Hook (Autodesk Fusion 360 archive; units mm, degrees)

design "Hook" references "Base"
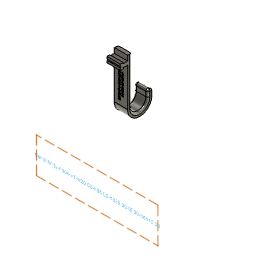
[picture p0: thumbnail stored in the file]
parameter "width" = 20
parameter "height" = 88
parameter "hook_diameter" = 36
parameter "thickness" = 6
parameter "hook_end_height" = 10
component_insert "Component Insert"
sketch "Sketch1" plane through (0, 55.6118, 0) normal (0, 1, 0) x axis (-1, 0, 0)
  line L1 (0, 52.6059) -> (-48, 52.6059)
  line L2 (0, 60) -> (0, 52.6059)
  line L3 (-48, 60) -> (0, 60)
  line L4 (-48, 52.6059) -> (-48, 60)
  line L5 (-48, 60) -> (0, 60)
sketch "Sketch2" plane through (0, 0, 0) normal (1, 0, 0) x axis (0, 1, 0)
  line L1 (55.6118, -28) -> (55.6118, 60)
  line L2 (91.6118, -28) -> (55.6118, -28)
  line L3 (91.6118, 8) -> (91.6118, -28)
  line L4 (55.6118, -28) -> (91.6118, 8)
  line L5 (91.6118, -10) -> (55.6118, -10)
  line L6 (61.6118, -28) -> (61.6118, 60)
  line L7 (61.6118, 59.3739) -> (55.6118, 60)
  circle C1 centre (73.6118, -10) radius 18
  circle C2 centre (73.6118, -10) radius 12
  point P2 (55.6118, 60)
  point P3 (55.6118, 60)
  point P7 (73.6118, -10)
  point P8 (55.6118, -10)
  point P9 (91.6118, -10)
  point P13 (55.6118, 60)
  point P14 (61.6118, 59.3739)
  point P4 (55.6118, -28)
  point P5 (91.6118, -28)
  point P6 (91.6118, 8)
  coincident P2 P3
  vertical L1
  perpendicular L1 L2
  perpendicular L2 L3
  midpoint L4 P7
  coincident L1 P8
  coincident C1 P8
  midpoint L3 P9
  perpendicular L3 L5
  coincident P2 P13
  coincident L6 P14
  dimension "d5" distance P3 P4 = 88 (= "height")
  dimension "d6" distance P4 P5 = 36 (= "hook_diameter")
  dimension "d8" distance P5 P6 = 36 (= "hook_diameter")
  dimension "d9" diameter C1 = 36 (= "hook_diameter")
  dimension "d11" = -6 (= "thickness * -1")
  dimension "d12" = -6 (= "thickness * -1")
extrude "Extrude1" new body sketch "Sketch2" profile of L1 C1 L5 L6 C2 L7 along normal blind 20 (= "width")
extrude "Extrude2" add of existing geometry blind 10 (= "hook_end_height")
fillet "Fillet1" radius 3 (= "thickness / 2")
extrude "Extrude3" new body of existing geometry blind 29
extrude "Extrude4" add of existing geometry to an object
extrude "Extrude5" cut of existing geometry to an object
sketch "Text" plane through (0, 55.6118, 0) normal (0, -1, 0) x axis (1, 0, 0)
  dimension "d29" = 3 (= "( if(height < 70 mm; if(height < 41 mm; 1.2; 2); 3) ) * 1 mm")
  dimension "d30" = 20 (= "width")
extrude "Extrude6" cut sketch "Text" against normal blind 2
sketch "Filename" plane through (0, 0, 0) normal (0, 1, 0) x axis (1, 0, 0)
  dimension "d31" = 5

design "Base"
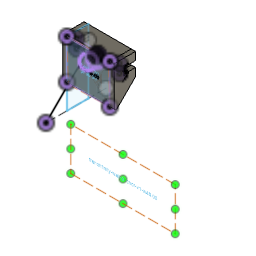
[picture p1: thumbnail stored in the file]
parameter "wall_anchor_height" = 60
parameter "wall_anchor_width" = 20
parameter "wall_anchor_angle" = 45
parameter "width_per_slot" = 40
parameter "slot_inner_width" = 8.5
parameter "slot_inner_height" = 4.5
parameter "slot_outer_width" = 5.6
parameter "slot_outer_height" = 6.5
parameter "slot_dept" = 15
parameter "print_tolerance" = 0.12
parameter "base_plate_thickness" = 16
parameter "base_plate_slot_height" = 50
parameter "wall_anchor_angle_rounded_border" = 1.5
parameter "base_plate_screw_hole_diameter" = 4
parameter "base_plate_screw_head_diameter" = 8
parameter "base_plate_screw_head_height" = 4
parameter "base_plate_screw_hole_side_distance" = 7
parameter "slot_screw_head_width" = 4.42 (= "4.3 mm + print_tolerance")
parameter "slot_screw_thread_width" = 2.12 (= "2 mm + print_tolerance")
parameter "slot_screw_head_height" = 2.12 (= "2 mm + print_tolerance")
parameter "width" = 48
parameter "filament_hole_width" = 1.7
parameter "plate_height" = 50
sketch "Side" plane through (0, 0, 0) normal (1, 0, 0) x axis (0, 1, 0)
  line L1 (39.6118, 0) -> (19.6118, 0)
  line L2 (39.6118, 60) -> (39.6118, 0)
  line L3 (19.6118, 60) -> (39.6118, 60)
  line L4 (19.6118, 0) -> (19.6118, 60)
  line L5 (39.6118, 39.6118) -> (0, 0)
  line L6 (56.0196, 0) -> (0, 0)
  point P1 (0, 0)
  point P6 (0, 0)
  point P7 (39.6118, 39.6118)
  point P2 (19.6118, 0)
  point P3 (39.6118, 0)
  point P5 (19.6118, 60)
  horizontal L1
  vertical L2
  horizontal L3
  vertical L4
  horizontal L6
  coincident P1 P6
  coincident L2 P7
  dimension "d4" distance P2 P3 = 20 (= "wall_anchor_width")
  dimension "d5" distance P2 P5 = 60 (= "wall_anchor_height")
  dimension "d6" angle L5 L6 = 45 (= "wall_anchor_angle")
extrude "Extrude1" new body sketch "Side" profile of L1 L2 L3 L4 L5 along normal blind 40 (= "width_per_slot")
sketch "Slot LeftToRight" plane through (0, 0, 0) normal (-1, 0, 0) x axis (0, -1, 0)
  line L1 (-19.6118, 60) -> (-19.6118, 19.6118)
  line L2 (-39.6118, 60) -> (-19.6118, 60)
  line L3 (-39.6118, 39.6118) -> (-39.6118, 60)
  line L4 (-19.6118, 19.6118) -> (-39.6118, 39.6118)
  line L5 (-39.6118, 52.6059) -> (-39.6118, 49.8059)
  line L6 (-39.6118, 47.0059) -> (-39.6118, 49.8059)
  line L7 (-33.1118, 52.6059) -> (-39.6118, 52.6059)
  line L8 (-28.6118, 49.8059) -> (-39.6118, 49.8059)
  line L9 (-28.6118, 54.0559) -> (-28.6118, 49.8059)
  line L10 (-33.1118, 54.0559) -> (-28.6118, 54.0559)
  line L11 (-33.1118, 52.6059) -> (-33.1118, 54.0559)
  line L12 (-28.6118, 45.5559) -> (-28.6118, 49.8059)
  line L13 (-33.1118, 45.5559) -> (-28.6118, 45.5559)
  line L14 (-33.1118, 47.0059) -> (-33.1118, 45.5559)
  line L15 (-33.1118, 47.0059) -> (-39.6118, 47.0059)
  point P6 (-39.6118, 49.8059)
  point P7 (-39.6118, 52.6059)
  point P17 (-39.6118, 47.0059)
  point P9 (-33.1118, 52.6059)
  point P16 (-33.1118, 47.0059)
  point P10 (-28.6118, 49.8059)
  point P13 (-28.6118, 49.8059)
  point P11 (-28.6118, 54.0559)
  point P14 (-28.6118, 45.5559)
  point P12 (-33.1118, 54.0559)
  point P15 (-33.1118, 45.5559)
  midpoint L3 P6
  parallel L3 L5
  parallel L3 L6
  perpendicular L3 L7
  perpendicular L6 L8
  perpendicular L8 L9
  perpendicular L9 L10
  symmetric P7 L8 P17
  symmetric P9 L8 P16
  symmetric P10 L8 P13
  symmetric L8 P11 P14
  symmetric L8 P12 P15
  dimension "d80" distance P6 P7 = 2.8 (= "slot_outer_width / 2")
  dimension "d82" distance P7 P9 = 6.5 (= "slot_outer_height")
  dimension "d84" distance P6 P10 = 11 (= "slot_outer_height + slot_inner_height")
  dimension "d85" distance P10 P11 = 4.25 (= "slot_inner_width / 2")
  dimension "d86" distance P11 P12 = 4.5 (= "slot_inner_height")
extrude "Extrude3" cut sketch "Slot LeftToRight" profile of L3 L5 L6 L7 L9 L10 L11 L12 L13 L14 L15 against normal blind 40 (magnitude of "width_per_slot * -1")
sketch "Plate" plane through (0, 39.6118, 0) normal (0, 1, 0) x axis (-1, 0, 0)
  line L1 (0, 39.6118) -> (-40, 39.6118)
  line L2 (-40, 60) -> (0, 60)
  line L3 (0, 10) -> (0, 60)
  line L4 (-40, 10) -> (-40, 60)
  line L5 (-40, 10) -> (0, 10)
  line L6 (-40, 47.0059) -> (0, 47.0059)
  line L7 (-40, 52.6059) -> (-40, 60)
  line L8 (0, 60) -> (0, 52.6059)
  line L9 (0, 52.6059) -> (-40, 52.6059)
  line L10 (-40, 60) -> (0, 60)
  line L11 (-40, 39.6118) -> (-40, 47.0059)
  line L12 (0, 47.0059) -> (0, 39.6118)
  point P2 (0, 60)
  point P3 (-40, 60)
  point P4 (0, 10)
  point P5 (-40, 10)
  perpendicular L1 L3
  perpendicular L1 L4
  dimension "d36" distance P2 P3 = 40 (= "width_per_slot")
  dimension "d37" distance P2 P4 = 50 (= "base_plate_slot_height")
  dimension "d39" distance P3 P5 = 50 (= "base_plate_slot_height")
extrude "Extrude6" new body sketch "Plate" profile of L1 L2 L3 L4 L5 L6 L7 L8 L9 L10 along normal blind 16 (= "base_plate_thickness") bodies "Base plate with slot"
sketch "Slot" plane through (0, 0, 0) normal (-1, 0, 0) x axis (0, -1, 0)
  line L1 (-19.6118, 60) -> (-19.6118, 19.6118)
  line L2 (-39.6118, 60) -> (-19.6118, 60)
  line L3 (-39.6118, 52.6059) -> (-39.6118, 60)
  line L4 (-33.1118, 52.6059) -> (-39.6118, 52.6059)
  line L5 (-33.1118, 54.0559) -> (-33.1118, 52.6059)
  line L6 (-28.6118, 54.0559) -> (-33.1118, 54.0559)
  line L7 (-28.6118, 45.5559) -> (-28.6118, 54.0559)
  line L8 (-33.1118, 45.5559) -> (-28.6118, 45.5559)
  line L9 (-33.1118, 47.0059) -> (-33.1118, 45.5559)
  line L10 (-39.6118, 47.0059) -> (-33.1118, 47.0059)
  line L11 (-39.6118, 39.6118) -> (-39.6118, 47.0059)
  line L12 (-19.6118, 19.6118) -> (-39.6118, 39.6118)
  line L13 (-33.1118, 52.6059) -> (-39.6118, 52.6059)
  line L14 (-33.1118, 54.0559) -> (-33.1118, 52.6059)
  line L15 (-28.6118, 54.0559) -> (-33.1118, 54.0559)
  line L16 (-28.6118, 45.5559) -> (-28.6118, 54.0559)
  line L17 (-33.1118, 45.5559) -> (-28.6118, 45.5559)
  line L18 (-33.1118, 47.0059) -> (-33.1118, 45.5559)
  line L19 (-39.6118, 47.0059) -> (-33.1118, 47.0059)
  line L20 (-39.6118, 10) -> (-39.6118, 60)
  line L21 (-32.9918, 52.4859) -> (-39.6118, 52.4859)
  line L22 (-32.9918, 53.9359) -> (-32.9918, 52.4859)
  line L23 (-28.7318, 53.9359) -> (-32.9918, 53.9359)
  line L24 (-28.7318, 45.6759) -> (-28.7318, 53.9359)
  line L25 (-32.9918, 45.6759) -> (-28.7318, 45.6759)
  line L26 (-32.9918, 47.1259) -> (-32.9918, 45.6759)
  line L27 (-39.6118, 47.1259) -> (-32.9918, 47.1259)
  line L28 (-33.1118, 52.6059) -> (-39.6118, 52.6059)
  line L29 (-33.1118, 52.6059) -> (-33.1118, 54.0559)
  line L30 (-28.6118, 54.0559) -> (-33.1118, 54.0559)
  line L31 (-28.6118, 45.5559) -> (-28.6118, 54.0559)
  line L32 (-33.1118, 45.5559) -> (-28.6118, 45.5559)
  line L33 (-33.1118, 47.0059) -> (-33.1118, 45.5559)
  line L34 (-39.6118, 47.0059) -> (-33.1118, 47.0059)
  line L35 (-39.6118, 47.0059) -> (-39.6118, 52.6059)
  line L36 (-49.1118, 52.6059) -> (-55.6118, 52.6059)
  line L37 (-49.1118, 52.6059) -> (-49.1118, 54.0559)
  line L38 (-44.6118, 54.0559) -> (-49.1118, 54.0559)
  line L39 (-44.6118, 45.5559) -> (-44.6118, 54.0559)
  line L40 (-49.1118, 45.5559) -> (-44.6118, 45.5559)
  line L41 (-49.1118, 47.0059) -> (-49.1118, 45.5559)
  line L42 (-55.6118, 47.0059) -> (-49.1118, 47.0059)
  line L43 (-55.6118, 47.0059) -> (-55.6118, 52.6059)
  point P15 (-39.6118, 52.6059)
  point P33 (-39.6118, 52.6059)
  point P16 (-33.1118, 52.6059)
  point P34 (-33.1118, 52.6059)
  point P17 (-33.1118, 54.0559)
  point P35 (-33.1118, 54.0559)
  point P36 (-33.1118, 52.6059)
  point P18 (-28.6118, 54.0559)
  point P37 (-28.6118, 54.0559)
  point P19 (-28.6118, 45.5559)
  point P38 (-28.6118, 45.5559)
  point P10 (-28.6118, 45.5559)
  point P39 (-28.6118, 45.5559)
  point P11 (-33.1118, 45.5559)
  point P40 (-33.1118, 45.5559)
  point P41 (-33.1118, 45.5559)
  point P12 (-33.1118, 47.0059)
  point P42 (-33.1118, 47.0059)
  point P21 (-33.1118, 47.0059)
  point P43 (-33.1118, 47.0059)
  point P22 (-39.6118, 47.0059)
  point P44 (-39.6118, 47.0059)
  point P45 (-39.6118, 52.6059)
  point P46 (-39.6118, 47.0059)
  coincident P15 P33
  coincident P16 P34
  coincident P17 P35
  coincident P16 P36
  coincident P18 P37
  coincident P19 P38
  coincident P10 P39
  coincident P11 P40
  coincident P11 P41
  coincident P12 P42
  coincident P21 P43
  coincident P22 P44
  coincident P15 P45
  coincident P22 P46
  dimension "d91" = 0.12 (= "print_tolerance")
  dimension "d96" R-Pattern1-uDistance = -16 (= "base_plate_thickness * -1")
  dimension "d97" R-Pattern1-vDistance = 0
extrude "Extrude7" add sketch "Slot" profile of L20 L24 L23 L27 L22 L25 L26 L21 against normal blind 40 (magnitude of "width_per_slot * -1")
extrude "Extrude8" cut sketch "Slot" profile of L36 L37 L38 L39 L40 L41 L42 L43 no distance stored
sketch "Sketch3" plane through (0, 0, 0) normal (-1, 0, 0) x axis (0, -1, 0)
  line L1 (-32.9918, 47.1259) -> (-39.6118, 47.1259)
  line L2 (-32.9918, 45.6759) -> (-32.9918, 47.1259)
  line L3 (-28.7318, 45.6759) -> (-32.9918, 45.6759)
  line L4 (-28.7318, 53.9359) -> (-28.7318, 45.6759)
  line L5 (-32.9918, 53.9359) -> (-28.7318, 53.9359)
  line L6 (-32.9918, 52.4859) -> (-32.9918, 53.9359)
  line L7 (-39.6118, 52.4859) -> (-32.9918, 52.4859)
  line L8 (-44.6118, 45.5559) -> (-44.6118, 54.0559)
  line L9 (-32.9918, 52.4859) -> (-39.6118, 52.4859)
  line L10 (-32.9918, 53.9359) -> (-32.9918, 52.4859)
  line L11 (-28.7318, 53.9359) -> (-32.9918, 53.9359)
  line L12 (-28.7318, 45.6759) -> (-28.7318, 53.9359)
  line L13 (-32.9918, 45.6759) -> (-28.7318, 45.6759)
  line L14 (-32.9918, 47.1259) -> (-32.9918, 45.6759)
  line L15 (-39.6118, 47.1259) -> (-32.9918, 47.1259)
  line L16 (-39.6118, 47.1259) -> (-39.6118, 52.4859)
  line L17 (-55.6118, 52.4859) -> (-48.9918, 52.4859)
  line L18 (-48.9918, 52.4859) -> (-48.9918, 53.9359)
  line L19 (-48.9918, 53.9359) -> (-44.7318, 53.9359)
  line L20 (-44.7318, 45.6759) -> (-44.7318, 53.9359)
  line L21 (-48.9918, 45.6759) -> (-44.7318, 45.6759)
  line L22 (-48.9918, 47.1259) -> (-48.9918, 45.6759)
  line L23 (-55.6118, 47.1259) -> (-48.9918, 47.1259)
  line L24 (-55.6118, 47.1259) -> (-55.6118, 52.4859)
  line L25 (-55.6118, 47.0059) -> (-49.1118, 47.0059)
  line L26 (-55.6118, 10) -> (-55.6118, 47.0059)
  line L27 (-39.6118, 10) -> (-55.6118, 10)
  line L28 (-39.6118, 47.1259) -> (-39.6118, 10)
  line L29 (-39.6118, 60) -> (-39.6118, 52.4859)
  line L30 (-55.6118, 60) -> (-39.6118, 60)
  line L31 (-55.6118, 52.6059) -> (-55.6118, 60)
  line L32 (-49.1118, 52.6059) -> (-55.6118, 52.6059)
  line L33 (-49.1118, 54.0559) -> (-49.1118, 52.6059)
  line L34 (-44.6118, 54.0559) -> (-49.1118, 54.0559)
  line L35 (-49.1118, 45.5559) -> (-44.6118, 45.5559)
  line L36 (-49.1118, 47.0059) -> (-49.1118, 45.5559)
  point P9 (-39.6118, 52.4859)
  point P20 (-39.6118, 52.4859)
  point P19 (-39.6118, 47.1259)
  point P21 (-39.6118, 47.1259)
  coincident P9 P20
  coincident P19 P21
  dimension "d105" R-Pattern1-vDistance = 0
extrude "Extrude3" new body sketch "Sketch3" profile of L17 L18 L19 L20 L21 L22 L23 L24 against normal blind 40 (magnitude of "width_per_slot * -1")
sketch "Screw hole" plane through (0, 28.6118, 0) normal (0, 1, 0) x axis (-1, 0, 0)
  line L1 (0, 54.0559) -> (0, 45.5559)
  line L2 (-40, 54.0559) -> (0, 54.0559)
  line L3 (-40, 45.5559) -> (-40, 54.0559)
  line L4 (0, 45.5559) -> (-40, 45.5559)
  line L5 (0, 45.5559) -> (-40, 54.0559)
  line L6 (-40, 45.5559) -> (0, 54.0559)
  circle C1 centre (-20, 49.8059) radius 2.21
  circle C2 centre (-20, 49.8059) radius 1.06
  point P4 (-40, 54.0559)
  point P6 (-40, 54.0559)
  point P2 (0, 45.5559)
  point P7 (0, 45.5559)
  point P3 (0, 54.0559)
  point P8 (0, 54.0559)
  point P5 (-40, 45.5559)
  point P9 (-40, 45.5559)
  point P10 (-20, 49.8059)
  coincident P4 P6
  coincident P2 P7
  coincident P3 P8
  coincident P5 P9
  midpoint L5 P10
  concentric C1 C2
  dimension "d119" diameter C1 = 4.42 (= "slot_screw_head_width")
  dimension "d120" diameter C2 = 2.12 (= "slot_screw_thread_width")
extrude "Extrude4" cut sketch "Screw hole" profile of C2 against normal blind 2000
extrude "Extrude5" cut sketch "Screw hole" profile of C1 C2 no distance stored
fillet "Fillet1" radius 1.5 (= "wall_anchor_angle_rounded_border")
work_plane "WorkPlane1" sketch "Slot LeftToRight" AlongDistance -20 (= "-width_per_slot / 2")
sketch "Screw head" plane through (20, 0, 0) normal (-1, 0, 0) x axis (0, -1, 0)
  line L1 (-28.6118, 52.0159) -> (-28.6118, 47.5959)
  line L2 (-26.4918, 52.0159) -> (-26.4918, 47.5959)
  line L3 (-26.4918, 48.7459) -> (-26.4918, 50.8659)
  line L4 (-26.4918, 50.8659) -> (-28.6118, 52.0159)
  line L5 (-26.4918, 52.0159) -> (-28.6118, 52.0159)
  point P3 (-28.6118, 52.0159)
  point P8 (-28.6118, 52.0159)
  point P6 (-26.4918, 50.8659)
  point P9 (-26.4918, 50.8659)
  point P10 (-28.6118, 52.0159)
  point P5 (-26.4918, 52.0159)
  point P11 (-26.4918, 52.0159)
  coincident P3 P8
  coincident P6 P9
  coincident P3 P10
  coincident P5 P11
revolve "Revolve1" sketch "Screw head" AlongAngle 360
sketch "Plate" plane through (0, 39.6118, 0) normal (0, 1, 0) x axis (-1, 0, 0)
  line L1 (0, 39.6118) -> (-40, 39.6118)
  line L2 (-40, 60) -> (0, 60)
  line L3 (0, 10) -> (0, 60)
  line L4 (-40, 10) -> (-40, 60)
  line L5 (-40, 10) -> (0, 10)
  line L6 (-40, 47.0059) -> (0, 47.0059)
  line L7 (-40, 39.6118) -> (-40, 47.0059)
  line L8 (0, 47.0059) -> (0, 39.6118)
  line L9 (0, 52.6059) -> (-40, 52.6059)
  line L10 (-40, 60) -> (0, 60)
  line L11 (0, 60) -> (0, 52.6059)
  line L12 (-40, 52.6059) -> (-40, 60)
  point P2 (0, 60)
  point P3 (-40, 60)
  point P4 (0, 10)
  point P5 (-40, 10)
  perpendicular L1 L3
  perpendicular L1 L4
  dimension "d36_1" distance P2 P3 = 40 (= "width_per_slot")
  dimension "d37_1" distance P2 P4 = 50 (= "base_plate_slot_height")
  dimension "d39_1" distance P3 P5 = 50 (= "base_plate_slot_height")
extrude "Extrude6" new body sketch "Plate" profile of L1 L2 L3 L4 L5 L6 L7 L8 L9 L10 along normal blind 16 (= "base_plate_thickness") named "d89_1" bodies "Base plate with slot"
sketch "Slot" plane through (0, 0, 0) normal (-1, 0, 0) x axis (0, -1, 0)
  line L1 (-19.6118, 60) -> (-19.6118, 23.2332)
  line L2 (-39.6118, 60) -> (-19.6118, 60)
  line L3 (-39.6118, 52.6059) -> (-39.6118, 60)
  line L4 (-33.1118, 52.6059) -> (-39.6118, 52.6059)
  line L5 (-33.1118, 54.0559) -> (-33.1118, 52.6059)
  line L6 (-28.6118, 54.0559) -> (-33.1118, 54.0559)
  line L7 (-28.6118, 45.5559) -> (-28.6118, 54.0559)
  line L8 (-33.1118, 45.5559) -> (-28.6118, 45.5559)
  line L9 (-33.1118, 47.0059) -> (-33.1118, 45.5559)
  line L10 (-39.6118, 47.0059) -> (-33.1118, 47.0059)
  line L11 (-39.6118, 39.6118) -> (-39.6118, 47.0059)
  line L12 (-22.1725, 22.1725) -> (-39.6118, 39.6118)
  line L13 (-33.1118, 52.6059) -> (-39.6118, 52.6059)
  line L14 (-33.1118, 54.0559) -> (-33.1118, 52.6059)
  line L15 (-28.6118, 54.0559) -> (-33.1118, 54.0559)
  line L16 (-28.6118, 45.5559) -> (-28.6118, 54.0559)
  line L17 (-33.1118, 45.5559) -> (-28.6118, 45.5559)
  line L18 (-33.1118, 47.0059) -> (-33.1118, 45.5559)
  line L19 (-39.6118, 47.0059) -> (-33.1118, 47.0059)
  line L20 (-39.6118, 10) -> (-39.6118, 60)
  line L21 (-32.9918, 52.4859) -> (-39.6118, 52.4859)
  line L22 (-32.9918, 53.9359) -> (-32.9918, 52.4859)
  line L23 (-28.7318, 53.9359) -> (-32.9918, 53.9359)
  line L24 (-28.7318, 45.6759) -> (-28.7318, 53.9359)
  line L25 (-32.9918, 45.6759) -> (-28.7318, 45.6759)
  line L26 (-32.9918, 47.1259) -> (-32.9918, 45.6759)
  line L27 (-39.6118, 47.1259) -> (-32.9918, 47.1259)
  line L28 (-33.1118, 52.6059) -> (-39.6118, 52.6059)
  line L29 (-33.1118, 52.6059) -> (-33.1118, 54.0559)
  line L30 (-28.6118, 54.0559) -> (-33.1118, 54.0559)
  line L31 (-28.6118, 45.5559) -> (-28.6118, 54.0559)
  line L32 (-33.1118, 45.5559) -> (-28.6118, 45.5559)
  line L33 (-33.1118, 47.0059) -> (-33.1118, 45.5559)
  line L34 (-39.6118, 47.0059) -> (-33.1118, 47.0059)
  line L35 (-39.6118, 47.0059) -> (-39.6118, 52.6059)
  line L36 (-49.1118, 52.6059) -> (-55.6118, 52.6059)
  line L37 (-49.1118, 52.6059) -> (-49.1118, 54.0559)
  line L38 (-44.6118, 54.0559) -> (-49.1118, 54.0559)
  line L39 (-44.6118, 45.5559) -> (-44.6118, 54.0559)
  line L40 (-49.1118, 45.5559) -> (-44.6118, 45.5559)
  line L41 (-49.1118, 47.0059) -> (-49.1118, 45.5559)
  line L42 (-55.6118, 47.0059) -> (-49.1118, 47.0059)
  line L43 (-55.6118, 47.0059) -> (-55.6118, 52.6059)
  arc A1 centre (-21.1118, 23.2332) radius 1.5 clockwise from (-19.6118, 23.2332) to (-22.1725, 22.1725)
  point P15 (-39.6118, 52.6059)
  point P33 (-39.6118, 52.6059)
  point P16 (-33.1118, 52.6059)
  point P34 (-33.1118, 52.6059)
  point P17 (-33.1118, 54.0559)
  point P35 (-33.1118, 54.0559)
  point P36 (-33.1118, 52.6059)
  point P18 (-28.6118, 54.0559)
  point P37 (-28.6118, 54.0559)
  point P19 (-28.6118, 45.5559)
  point P38 (-28.6118, 45.5559)
  point P10 (-28.6118, 45.5559)
  point P39 (-28.6118, 45.5559)
  point P11 (-33.1118, 45.5559)
  point P40 (-33.1118, 45.5559)
  point P41 (-33.1118, 45.5559)
  point P12 (-33.1118, 47.0059)
  point P42 (-33.1118, 47.0059)
  point P21 (-33.1118, 47.0059)
  point P43 (-33.1118, 47.0059)
  point P22 (-39.6118, 47.0059)
  point P44 (-39.6118, 47.0059)
  point P45 (-39.6118, 52.6059)
  point P46 (-39.6118, 47.0059)
  coincident P15 P33
  coincident P16 P34
  coincident P17 P35
  coincident P16 P36
  coincident P18 P37
  coincident P19 P38
  coincident P10 P39
  coincident P11 P40
  coincident P11 P41
  coincident P12 P42
  coincident P21 P43
  coincident P22 P44
  coincident P15 P45
  coincident P22 P46
  dimension "d91_1" = 0.12 (= "print_tolerance")
  dimension "d96_1" R-Pattern1-uDistance = -16 (= "base_plate_thickness * -1")
  dimension "d97_1" R-Pattern1-vDistance = 0
extrude "Extrude8" cut sketch "Slot" profile of L36 L37 L38 L39 L40 L41 L42 L43 no distance stored
sketch "Screw" plane through (0, 55.6118, 0) normal (0, 1, 0) x axis (-1, 0, 0)
  line L1 (-40, 47.0059) -> (0, 47.0059)
  line L2 (-40, 10) -> (-40, 47.0059)
  line L3 (0, 10) -> (-40, 10)
  line L4 (0, 47.0059) -> (0, 10)
  line L5 (-33, 17) -> (-33, 40.0059)
  line L6 (-7, 17) -> (-33, 17)
  line L7 (-7, 40.0059) -> (-7, 17)
  line L8 (-33, 40.0059) -> (-7, 40.0059)
  circle C1 centre (-33, 17) radius 4
  circle C2 centre (-33, 17) radius 2
  point P7 (-33, 17)
  point P10 (-33, 17)
  coincident P7 P10
  concentric C1 C2
  dimension "d127" = -7 (= "base_plate_screw_hole_side_distance * -1")
  dimension "d128" diameter C1 = 8
  dimension "d129" diameter C2 = 4
rectangular_pattern "R-Pattern2" countU 1 (= "floor(( width / mm ) / ( width_per_slot / cm * 10 ))") uSpaceDistance 40 (= "width_per_slot") vSpaceDistance 0
work_plane "WorkPlane2"
extrude "Extrude12" new body of existing geometry no distance stored
mirror "Mirror3" mirrorStitchTolerance 0.1
sketch "filename" plane through (0, 19.6118, 0) normal (0, -1, 0) x axis (1, 0, 0)
  dimension "d216" = 3
sketch "Text" plane through (0, 19.6118, 0) normal (0, -1, 0) x axis (1, 0, 0)
  line L1 (44, 60) -> (44, 23.2332)
  line L2 (40, 23.2332) -> (40, 60)
  line L3 (44, 23.2332) -> (40, 23.2332)
  line L4 (44, 60) -> (44, 23.2332)
  line L5 (40, 60) -> (44, 60)
  line L6 (0, 60) -> (0, 23.2332)
  line L7 (-4, 60) -> (0, 60)
  line L8 (-4, 23.2332) -> (-4, 60)
  line L9 (0, 23.2332) -> (-4, 23.2332)
  curve K1
  curve K2
  curve K3
  curve K4
  line L10 (80, 60) -> (40, 60)
  point P4 (44, 23.2332)
  point P2 (-4, 60)
  coincident P4
  coincident P2
  parallel K3 L10
  dimension "d229" Text1-Height = 3
extrude "Extrude19" cut sketch "Text" against normal blind 2
extrude "Extrude14" cut of existing geometry blind 4 (= "( width_per_slot - width ) / -2")
extrude "Extrude15" cut of existing geometry blind 4 (= "( width_per_slot - width ) / -2")
extrude "Extrude9" cut of existing geometry blind -39 (= "-width_per_slot + 1 mm")
extrude "Extrude10" add of existing geometry blind 47 (= "width - 1 mm")
extrude "Extrude13" cut of existing geometry blind -30
extrude "Extrude14" add of existing geometry blind 50 (= "plate_height")
sketch "Sketch7" plane through (0, 39.6118, 0) normal (0, -1, 0) x axis (1, 0, 0)
  dimension "d236" = 3
extrude "Extrude11" cut sketch "Sketch7" against normal blind 2
sketch "File name" plane through (0, 39.6118, 0) normal (0, -1, 0) x axis (1, 0, 0)
  line L1 (18.0624, 22.4163) -> (17.825, 22.4163)
  line L2 (18.0624, 19.404) -> (18.0624, 22.4163)
  line L3 (17.6941, 19.404) -> (18.0624, 19.404)
  line L4 (17.6941, 21.7512) -> (17.6941, 19.404)
  curve K1 (17.3441, 21.4975) -> (17.6941, 21.7512)
  curve K2 (16.9574, 21.3072) -> (17.3441, 21.4975)
  line L5 (16.9574, 21.6632) -> (16.9574, 21.3072)
  curve K3 (17.4976, 22.0152) -> (16.9574, 21.6632)
  curve K4 (17.825, 22.4163) -> (17.4976, 22.0152)
  line L6 (21.2896, 19.404) -> (21.7295, 21.0759)
  line L7 (20.9048, 19.404) -> (21.2896, 19.404)
  line L8 (20.2398, 21.5773) -> (20.9048, 19.404)
  line L9 (20.6204, 21.5773) -> (20.2398, 21.5773)
  line L10 (20.9662, 20.3228) -> (20.6204, 21.5773)
  line L11 (21.0952, 19.8563) -> (20.9662, 20.3228)
  curve K5 (21.2077, 20.3044) -> (21.0952, 19.8563)
  line L12 (21.5535, 21.5773) -> (21.2077, 20.3044)
  line L13 (21.9321, 21.5773) -> (21.5535, 21.5773)
  line L14 (22.2575, 20.3167) -> (21.9321, 21.5773)
  line L15 (22.366, 19.9013) -> (22.2575, 20.3167)
  line L16 (22.4908, 20.3208) -> (22.366, 19.9013)
  line L17 (22.8632, 21.5773) -> (22.4908, 20.3208)
  line L18 (23.2213, 21.5773) -> (22.8632, 21.5773)
  line L19 (22.542, 19.404) -> (23.2213, 21.5773)
  line L20 (22.1593, 19.404) -> (22.542, 19.404)
  line L21 (21.8134, 20.7055) -> (22.1593, 19.404)
  line L22 (21.7295, 21.0759) -> (21.8134, 20.7055)
  line L23 (20.0965, 20.3044) -> (20.0965, 20.6748)
  line L24 (18.9649, 20.3044) -> (20.0965, 20.3044)
  line L25 (18.9649, 20.6748) -> (18.9649, 20.3044)
  line L26 (20.0965, 20.6748) -> (18.9649, 20.6748)
  line L27 (15.6293, 19.404) -> (16.4519, 21.5773)
  line L28 (15.2855, 19.404) -> (15.6293, 19.404)
  line L29 (14.4587, 21.5773) -> (15.2855, 19.404)
  line L30 (14.8475, 21.5773) -> (14.4587, 21.5773)
  line L31 (15.3141, 20.2758) -> (14.8475, 21.5773)
  curve K6 (15.4533, 19.8379) -> (15.3141, 20.2758)
  curve K7 (15.5904, 20.2512) -> (15.4533, 19.8379)
  line L32 (16.0733, 21.5773) -> (15.5904, 20.2512)
  line L33 (16.4519, 21.5773) -> (16.0733, 21.5773)
  line L34 (0, 47.1259) -> (48, 47.1259)
  line L35 (0, -10) -> (0, 47.1259)
  line L36 (48, 47.1259) -> (48, -10)
  curve K8
  curve K9
  curve K10
  curve K11
  curve K12 (25.8755, 21.6428) -> (25.986, 21.2703)
  line L37 (48, -10) -> (0, -10)
  line L38 (24.6088, 20.1223) -> (24.6088, 19.404)
  curve K13 (25.986, 21.2703) -> (26.3257, 21.0309)
  curve K14 (27.4594, 19.6148) -> (27.7316, 20.2615)
  curve K15 (29.6879, 22.2403) -> (29.3625, 21.7389)
  line L39 (23.3073, 20.1223) -> (24.6088, 20.1223)
  curve K16 (25.368, 17.3556) -> (25.0672, 17.6359)
  curve K17 (25.5542, 16.9095) -> (25.368, 17.3556)
  curve K18 (19.7404, 16.5411) -> (20.0495, 16.6271)
  curve K19 (22.2984, 14.9736) -> (21.9199, 15.1148)
  curve K20 (30.2323, 22.4163) -> (29.6879, 22.2403)
  curve K21 (30.6559, 22.3181) -> (30.2323, 22.4163)
  curve K22 (30.9567, 22.0377) -> (30.6559, 22.3181)
  curve K23 (31.1429, 21.5916) -> (30.9567, 22.0377)
  curve K24 (18.5535, 16.3958) -> (18.2323, 16.801)
  curve K25 (27.5945, 17.5582) -> (27.2691, 17.0568)
  curve K26 (28.1388, 17.7342) -> (27.5945, 17.5582)
  curve K27 (28.5624, 17.6359) -> (28.1388, 17.7342)
  curve K28 (28.8632, 17.3556) -> (28.5624, 17.6359)
  curve K29 (29.0495, 16.9095) -> (28.8632, 17.3556)
  curve K30 (20.5447, 16.8481) -> (20.1252, 16.9443)
  curve K31 (32.9867, 22.3181) -> (32.5631, 22.4163)
  curve K32 (33.2875, 22.0377) -> (32.9867, 22.3181)
  curve K33 (33.4737, 21.5916) -> (33.2875, 22.0377)
  curve K34 (21.9199, 15.1148) -> (21.7214, 15.5404)
  curve K35 (29.3625, 21.7389) -> (29.2541, 20.8836)
  curve K36 (27.2691, 17.0568) -> (27.1606, 16.2014)
  curve K37 (31.1941, 17.3556) -> (30.8932, 17.6359)
  curve K38 (31.3803, 16.9095) -> (31.1941, 17.3556)
  curve K39 (29.5999, 17.0568) -> (29.4915, 16.2014)
  curve K40 (29.9253, 17.5582) -> (29.5999, 17.0568)
  curve K41 (30.4696, 17.7342) -> (29.9253, 17.5582)
  curve K42 (30.8932, 17.6359) -> (30.4696, 17.7342)
  curve K43 (17.3789, 16.8604) -> (17.1108, 16.6128)
  curve K44 (17.7411, 16.9443) -> (17.3789, 16.8604)
  curve K45 (18.2323, 16.801) -> (17.7411, 16.9443)
  curve K46 (22.3905, 16.711) -> (21.8237, 16.5227)
  curve K47 (23.0535, 16.4388) -> (22.3905, 16.711)
  curve K48 (23.3237, 15.7389) -> (23.0535, 16.4388)
  curve K49 (23.0863, 15.035) -> (23.3237, 15.7389)
  curve K50 (22.2984, 14.6707) -> (23.0863, 15.035)
  curve K51 (21.6293, 14.8999) -> (22.2984, 14.6707)
  curve K52 (21.3346, 15.5077) -> (21.6293, 14.8999)
  curve K53 (23.7739, 17.0568) -> (23.6654, 16.2014)
  curve K54 (24.0992, 17.5582) -> (23.7739, 17.0568)
  curve K55 (24.6436, 17.7342) -> (24.0992, 17.5582)
  curve K56 (25.0672, 17.6359) -> (24.6436, 17.7342)
  curve K57 (31.6934, 21.7389) -> (31.5849, 20.8836)
  curve K58 (32.0188, 22.2403) -> (31.6934, 21.7389)
  curve K59 (32.5631, 22.4163) -> (32.0188, 22.2403)
  curve K60 (26.1108, 22.1932) -> (25.8755, 21.6428)
  curve K61 (26.737, 22.4163) -> (26.1108, 22.1932)
  curve K62 (26.7432, 19.3529) -> (27.4594, 19.6148)
  curve K63 (26.0269, 19.6148) -> (26.7432, 19.3529)
  curve K64 (25.7548, 20.2717) -> (26.0269, 19.6148)
  curve K65 (25.9021, 20.7608) -> (25.7548, 20.2717)
  curve K66 (26.3257, 21.0309) -> (25.9021, 20.7608)
  line L40 (24.9771, 19.404) -> (24.9771, 20.1223)
  line L41 (24.9771, 22.404) -> (24.6763, 22.404)
  line L42 (25.3823, 20.1223) -> (25.3823, 20.46)
  line L43 (24.9771, 20.1223) -> (25.3823, 20.1223)
  line L44 (28.2964, 19.8235) -> (28.2964, 19.404)
  line L45 (28.7159, 19.8235) -> (28.2964, 19.8235)
  curve K67 (31.4478, 16.2014) -> (31.3803, 16.9095)
  curve K68 (31.3394, 15.3481) -> (31.4478, 16.2014)
  curve K69 (31.014, 14.8467) -> (31.3394, 15.3481)
  curve K70 (30.4696, 14.6707) -> (31.014, 14.8467)
  line L46 (16.7752, 16.8952) -> (16.7752, 13.889)
  curve K71 (18.662, 15.8249) -> (18.5535, 16.3958)
  curve K72 (18.5413, 15.2233) -> (18.662, 15.8249)
  curve K73 (18.1934, 14.814) -> (18.5413, 15.2233)
  curve K74 (17.7145, 14.6728) -> (18.1934, 14.814)
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  dimension "d239" Text1-Height = 3
sketch "Sketch4" plane through (40, 0, 0) normal (1, 0, 0) x axis (0, 1, 0)
  line L1 (44.7318, 53.9359) -> (48.9918, 53.9359)
  line L2 (44.7318, 45.6759) -> (44.7318, 53.9359)
  line L3 (48.9918, 45.6759) -> (44.7318, 45.6759)
  line L4 (48.9918, 47.1259) -> (48.9918, 45.6759)
  line L5 (55.6118, 47.1259) -> (48.9918, 47.1259)
  line L6 (55.6118, 52.4859) -> (55.6118, 47.1259)
  line L7 (48.9918, 52.4859) -> (55.6118, 52.4859)
  line L8 (48.9918, 53.9359) -> (48.9918, 52.4859)
  circle C1 centre (44.7318, 49.8059) radius 0.85
  point P10 (44.7318, 49.8059)
  midpoint L2 P10
  dimension "d241" diameter C1 = 1.7 (= "filament_hole_width")
extrude "Extrude4" cut sketch "Sketch4" profile of L2 C1 no distance stored
sketch "Sketch15" plane through (-4, 0, 0) normal (-1, 0, 0) x axis (0, -1, 0)
  line L1 (-19.6118, 60) -> (-19.6118, 23.2332)
  line L2 (-39.6118, 60) -> (-19.6118, 60)
  line L3 (-39.6118, 52.6059) -> (-39.6118, 60)
  line L4 (-33.1118, 52.6059) -> (-39.6118, 52.6059)
  line L5 (-33.1118, 54.0559) -> (-33.1118, 52.6059)
  line L6 (-28.6118, 54.0559) -> (-33.1118, 54.0559)
  line L7 (-28.6118, 45.5559) -> (-28.6118, 54.0559)
  line L8 (-33.1118, 45.5559) -> (-28.6118, 45.5559)
  line L9 (-33.1118, 47.0059) -> (-33.1118, 45.5559)
  line L10 (-39.6118, 47.0059) -> (-33.1118, 47.0059)
  line L11 (-39.6118, 39.6118) -> (-39.6118, 47.0059)
  line L12 (-22.1725, 22.1725) -> (-39.6118, 39.6118)
  arc A1 centre (-21.1118, 23.2332) radius 1.5 clockwise from (-19.6118, 23.2332) to (-22.1725, 22.1725)
  circle C1 centre (-28.6118, 49.8059) radius 0.85
  point P16 (-28.6118, 49.8059)
  midpoint L7 P16
  dimension "d244" diameter C1 = 1.7 (= "filament_hole_width")
sketch "Sketch9" plane through (48, 0, 0) normal (1, 0, 0) x axis (0, 1, 0)
  line L1 (49.1118, 47.0059) -> (55.6118, 47.0059)
  line L2 (49.1118, 45.5559) -> (49.1118, 47.0059)
  line L3 (44.6118, 45.5559) -> (49.1118, 45.5559)
  line L4 (44.6118, 54.0559) -> (44.6118, 45.5559)
  line L5 (49.1118, 54.0559) -> (44.6118, 54.0559)
  line L6 (49.1118, 52.6059) -> (49.1118, 54.0559)
  line L7 (55.6118, 52.6059) -> (49.1118, 52.6059)
  line L8 (55.6118, 47.0059) -> (55.6118, -10)
  line L9 (39.6118, 60) -> (55.6118, 60)
  line L10 (39.6118, 52.4859) -> (39.6118, 60)
  line L11 (32.9918, 52.4859) -> (39.6118, 52.4859)
  line L12 (32.9918, 53.9359) -> (32.9918, 52.4859)
  line L13 (28.7318, 53.9359) -> (32.9918, 53.9359)
  line L14 (28.7318, 45.6759) -> (28.7318, 53.9359)
  line L15 (32.9918, 45.6759) -> (28.7318, 45.6759)
  line L16 (32.9918, 47.1259) -> (32.9918, 45.6759)
  line L17 (39.6118, 47.1259) -> (32.9918, 47.1259)
  line L18 (55.6118, 60) -> (55.6118, 52.6059)
  line L19 (39.6118, -10) -> (39.6118, 47.1259)
  line L20 (55.6118, -10) -> (39.6118, -10)
  circle C1 centre (28.7318, 49.8059) radius 0.85
  circle C2 centre (44.6118, 49.8059) radius 0.85
  point P20 (28.7318, 49.8059)
  point P21 (44.6118, 49.8059)
  midpoint L14 P20
  midpoint L4 P21
  dimension "d247" diameter C1 = 1.7 (= "filament_hole_width")
  dimension "d250" diameter C2 = 1.7 (= "filament_hole_width")
extrude "Extrude12" cut sketch "Sketch9" profile of L4 L14 C1 C2 no distance stored
sketch "Sketch16" plane through (0, 19.6118, 0) normal (0, -1, 0) x axis (1, 0, 0)
  dimension "d253" = 3
extrude "Extrude22" cut sketch "Sketch16" against normal blind 2
extrude "Extrude23" cut sketch "Sketch15" profile of L7 C1 against normal blind 260 and along normal blind 80
sketch "Sketch17" plane through (0, 19.6118, 0) normal (0, -1, 0) x axis (1, 0, 0)
  dimension "d258" = 3
extrude "Extrude24" cut sketch "Sketch17" against normal blind 2
extrude "Extrude26" cut sketch "Text" against normal blind 2
extrude "Extrude27" cut sketch "Text" against normal blind 2
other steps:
create_component "CreateComponent1"
create_component "CreateComponent2"
create_component "CreateComponent3"
create_component "CreateComponent4"
named bodies: "Wall anchor part", "Base plate with slot"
